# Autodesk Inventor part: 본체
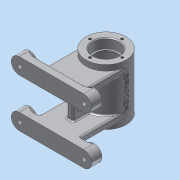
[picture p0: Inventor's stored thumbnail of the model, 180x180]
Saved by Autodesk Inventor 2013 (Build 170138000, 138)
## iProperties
Created: 2015-11
Part Number: 본체
Material: 알루미늄 6061
Document SubType Name: Modeling
Designer: Administrator
Density: 2.71 g/cm^3
Mass: 358.668 g
Surface Area: 461.393 cm^2
Volume: 132.35 cm^3
Author: Administrator
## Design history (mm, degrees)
sketch "스케치1"
  geometry: C1 r 25 at (0, 0); 1 further point
  constraints: 1 centre point, 1 coincident
  dimensions: "d0" = 50 diameter of C1
extrude "돌출1" new body sketch "스케치1" stored distance "d2" = 70; taper "d3" = 0 deg
sketch "스케치2"
  geometry: C1 r 21 at (0, 0); 1 further point
  constraints: 1 centre point, 1 coincident
  dimensions: "d4" = 42 diameter of C1
extrude "돌출2" cut sketch "스케치2" stored distance "d6" = 42; taper "d7" = 0 deg
hole "구멍1" diameter "d10" = 28; stored, may be unused: countersink angle "d14" = 90 deg, drill point angle "d16" = 0 deg; dims "d8" = 10, "d9" = 10, "d11" = 6, "d12" = 32, "d13" = 12, "d15" = 14
sketch "스케치3"
  geometry: C1 r 16 at (0, 0) reference; 1 further point
  constraints: 1 vertical alignment
  dimensions: "d17" = 20 distance of point (0, 20) C1.centre
hole "구멍2" sketch "스케치3" at (0, 20) diameter "d18" = 3.242; stored, may be unused: countersink angle "d22" = 90 deg, drill point angle "d24" = 118 deg; dims "d19" = 8, "d20" = 32, "d21" = 12, "d23" = 10
node "작업 평면1"
sketch "스케치4"
  geometry: C1 r 5 at (0, 0); 1 further point
  constraints: 1 centre point, 1 coincident
  dimensions: "d29" = 10 diameter of C1
extrude "돌출3" join sketch "스케치4" stored distance "d31" = 42; taper "d32" = 0 deg
hole "구멍3" diameter "d35" = 5.188; stored, may be unused: countersink angle "d39" = 90 deg, drill point angle "d41" = 0 deg; dims "d33" = 10, "d34" = 10, "d36" = 8, "d37" = 32, "d38" = 12, "d40" = 10
sketch "스케치5"
  geometry: L1 (0, 0)-(-14, -24.249); L2 (0, 0)-(28, 0)
  constraints: 4 end point, 1 equal length, 1 horizontal
  dimensions: "d42" = 28 distance of L1.start L1.end; "d43" = 120 deg angle of L1 L2
node "작업 평면2"
sketch "스케치6"
  geometry: C1 r 6 at (0, 0); 1 further point
  constraints: 1 centre point, 1 coincident
  dimensions: "d44" = 12 diameter of C1
extrude "돌출4" join sketch "스케치6" stored distance "d46" = 42; taper "d47" = 0 deg
hole "구멍4" diameter "d50" = 5.188; stored, may be unused: countersink angle "d54" = 90 deg, drill point angle "d56" = 0 deg; dims "d48" = 10, "d49" = 10, "d51" = 8, "d52" = 32, "d53" = 12, "d55" = 10
node "작업 평면3"
sketch "스케치7"
  geometry: L1 (40, 20)-(-40, 20); L2 (-40, 20)-(-40, 40); L3 (-40, 40)-(40, 40); L4 (40, 40)-(40, 20); C1 r 10 at (40, 30); 3 further points
  constraints: 8 end point, 3 midpoint, 2 parallel, 2 vertical alignment, 1 centre point, 1 horizontal, 1 perpendicular, 2 other
  dimensions: "d58" = 20 distance of L1.end L2.end; "d60" = 40 distance from line of L3 point (0, 0); "d61" = 80 distance of L2.end L3.end; "d62" = 10 radius of C1
extrude "돌출5" join sketch "스케치7" distance "d63" = 13; taper "d64" = 0 deg
extrude "돌출6" join sketch "스케치7" distance "d65" = 10; taper "d66" = 0 deg
sketch "스케치8"
  geometry: L1 (0, 10)-(80, 10) reference; L2 (0, 10)-(80, 10) reference; L3 (80, 0)-(80, 10) reference; L4 (80, 0)-(0, 0) reference; L5 (0, 0)-(0, 10) reference; L6 (0, 10)-(0, 13) reference; L7 (80, 10)-(80, 13) reference; L8 (65, 68)-(65, 10); L9 (15, 68)-(15, 10); C1 r 21 at (40, 68) reference; A1 r 25 centre (40, 68) between (65, 68) and (15, 68) reference; 1 further point
  constraints: 4 end point, 2 perpendicular, 2 point on circle, 2 point on line, 2 tangent
extrude "돌출7" join sketch "스케치8" distance "d67" = 8; taper "d68" = 0 deg
hole "구멍5" diameter "d71" = 6; stored, may be unused: countersink angle "d75" = 90 deg, drill point angle "d77" = 0 deg; dims "d69" = 10, "d70" = 10, "d72" = 8, "d73" = 12, "d74" = 4, "d76" = 10
sketch "스케치9"
  geometry: L1 (0, 10)-(0, 0) reference; L2 (36, 43.322)-(36, 23); L3 (36, 23)-(44, 23); L4 (44, 23)-(44, 43.322); A1 r 25 centre (40, 68) between (15, 68) and (65, 68) reference; 1 further point
  constraints: 6 end point, 2 parallel, 2 point on circle, 1 midpoint, 1 perpendicular, 1 vertical alignment
  dimensions: "d78" = 8 distance of L2.end L3.end; "d80" = 45 distance from line of L3 A1.centre
extrude "돌출8" join sketch "스케치9" stored distance "d81" = 8; taper "d82" = 0 deg
sketch "스케치10"
  geometry: L1 (20, -23)-(0, -23) reference; L2 (-28, 13.5)-(-12, 13.5); L3 (-12, 6.5)-(-28, 6.5); A1 r 3.5 centre (-12, 10) between (-12, 6.5) and (-12, 13.5); A2 r 3.5 centre (-28, 10) between (-28, 13.5) and (-28, 6.5); 2 further points
  constraints: 4 end point, 4 point on circle, 4 tangent, 2 centre point, 1 equal radius, 1 horizontal alignment, 1 midpoint, 1 vertical alignment
  dimensions: "d83" = 7 diameter of A1; "d87" = 33 distance from line of L1 A1.centre; "d108" = 23 dimension on A1 A2
extrude "돌출9" cut sketch "스케치10" stored distance "d88" = 8; taper "d89" = 0 deg
node "작업 평면4"
sketch "스케치11"
  geometry: 2 further points
  constraints: 1 coincident, 1 other
feature "엠보싱1" sketch "스케치11" dims "d90" = 0.5, "d91" = 0
fillet "모깎기1" dims "d92" = 0.3
chamfer "모따기1" distance "d93" = 1; stored, may be unused: second distance "d94" = 2, angle "d95" = 45 deg
fillet "모깎기2" dims "d96" = 0.3
chamfer "모따기2" distance "d97" = 1; stored, may be unused: second distance "d98" = 2, angle "d99" = 45 deg
fillet "모깎기3" dims "d100" = 3
fillet "모깎기4" dims "d101" = 2
fillet "모깎기5" dims "d102" = 2
fillet "모깎기6" dims "d103" = 2
fillet "모깎기7" dims "d104" = 2
fillet "모깎기8" dims "d105" = 2
fillet "모깎기9" dims "d106" = 2
fillet "모깎기10" dims "d107" = 2
node "솔리드1"
pattern_circular "원형 패턴1" dims angle "d26" = 360 deg
mirror "대칭1"
mirror "대칭2"
mirror "대칭3"
node "절단 모서리 투영1"
other parameters: "d28" = 28, "d57" = -68
